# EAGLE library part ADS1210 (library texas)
24-Bit ANALOG-TO-DIGITAL CONVERTER Source: http://focus.ti.com/lit/ds/symlink/ads1210.pdf
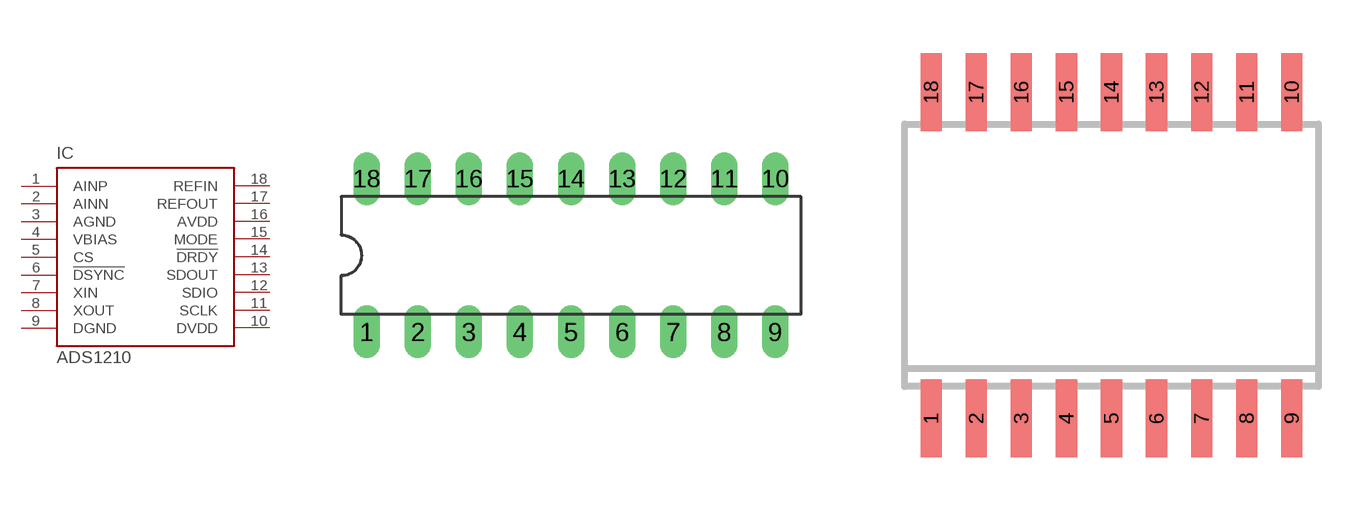
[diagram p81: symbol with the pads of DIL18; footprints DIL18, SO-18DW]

Designator prefix IC

## ADS1210P (MF: TEXAS INSTRUMENTS; MPN: ADS1210P; OC_FARNELL: 1312336; OC_NEWARK: 96K4580)  [DIL18]
1  AINP  in
2  AINN  in
3  AGND  pwr
4  VBIAS  in
5  CS  in
6  !DSYNC  in
7  XIN  in
8  XOUT  out
9  DGND  pwr
10  DVDD  pwr
11  SCLK
12  SDIO
13  SDOUT  out
14  !DRDY  out
15  MODE  in
16  AVDD  pwr
17  REFOUT  out
18  REFIN  in

## ADS1210U (MF: TEXAS INSTRUMENTS; MPN: ADS1210U; OC_FARNELL: 1295983; OC_NEWARK: 74K3627)  [SO-18DW]
Pads as for DIL18

## Footprint DIL18 (pad centres in mm)
Dual In Line Package
drill 0.813 long: 1 -10.16,-3.81; 2 -7.62,-3.81; 3 -5.08,-3.81; 4 -2.54,-3.81; 5 0,-3.81; 6 2.54,-3.81; 7 5.08,-3.81; 8 7.62,-3.81; 9 10.16,-3.81; 10 10.16,3.81; 11 7.62,3.81; 12 5.08,3.81; 13 2.54,3.81; 14 0,3.81; 15 -2.54,3.81; 16 -5.08,3.81; 17 -7.62,3.81; 18 -10.16,3.81

## Footprint SO-18DW (pad centres in mm)
Small Outline Integrated Circuit wide
smd 0.6 x 2.2: 1 -5.08,-4.6; 2 -3.81,-4.6; 3 -2.54,-4.6; 4 -1.27,-4.6; 5 0,-4.6; 6 1.27,-4.6; 7 2.54,-4.6; 8 3.81,-4.6; 9 5.08,-4.6; 10 5.08,4.6; 11 3.81,4.6; 12 2.54,4.6; 13 1.27,4.6; 14 0,4.6; 15 -1.27,4.6; 16 -2.54,4.6; 17 -3.81,4.6; 18 -5.08,4.6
